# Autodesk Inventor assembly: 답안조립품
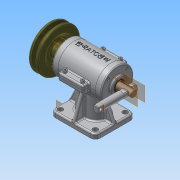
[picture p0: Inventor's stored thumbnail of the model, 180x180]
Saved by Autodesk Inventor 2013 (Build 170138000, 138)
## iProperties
Created: 2015-05
Part Number: 답안조립품
Document SubType Name: Assembly
Designer: Administrator
Author: Administrator
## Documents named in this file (18)
- C:\Users\Administrator\Desktop\350508V1051\답안조립품.iam
- C:\Users\Administrator\Desktop\350508V1051\M3x0.5x8.ipt
- C:\Users\Administrator\Desktop\350508V1051\M4x0.5x14.ipt
- C:\Users\Administrator\Desktop\350508V1051\V-벨트풀리.ipt
- C:\Users\Administrator\Desktop\350508V1051\가변스프링.ipt
- C:\Users\Administrator\Desktop\350508V1051\너트 M8.ipt
- C:\Users\Administrator\Desktop\350508V1051\뒤커버.ipt
- C:\Users\Administrator\Desktop\350508V1051\링크.ipt
- C:\Users\Administrator\Desktop\350508V1051\멈춤나사.ipt
- C:\Users\Administrator\Desktop\350508V1051\베어링 6201.ipt
- C:\Users\Administrator\Desktop\350508V1051\베어링 6202.ipt
- C:\Users\Administrator\Desktop\350508V1051\본체 커버.ipt
- C:\Users\Administrator\Desktop\350508V1051\본체.ipt
- C:\Users\Administrator\Desktop\350508V1051\슬라이드.ipt
- C:\Users\Administrator\Desktop\350508V1051\앞커버.ipt
- C:\Users\Administrator\Desktop\350508V1051\오일실.ipt
- C:\Users\Administrator\Desktop\350508V1051\키4x4.ipt
- C:\Users\Administrator\Desktop\350508V1051\편심축.ipt
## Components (15 placed, 5 different names)
1. 가변스프링:1
2. V-벨트풀리:1 — 플러쉬:1
3. M4x0.5x14:1
4. KS B 1012 C - 미터 C M8:1
5. M4x0.5x14:2
6. M4x0.5x14:3
7. M4x0.5x14:4
8. M3x0.5x8:2
9. M3x0.5x8:3
10. M3x0.5x8:4
11. M3x0.5x8:5
12. M3x0.5x8:1
13. M3x0.5x8:6
14. M3x0.5x8:7
15. M3x0.5x8:8
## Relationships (1: Flush 1)
- 플러쉬:1 [Flush]: V-벨트풀리:1
